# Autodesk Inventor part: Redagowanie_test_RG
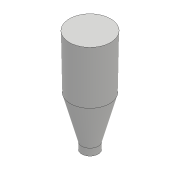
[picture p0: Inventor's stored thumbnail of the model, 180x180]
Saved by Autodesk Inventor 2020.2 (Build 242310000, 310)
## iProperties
Created: 2015-11
Part Number: Redagowanie_test_RG
Material: Ogólne
Document SubType Name: Modeling
Designer: F.Stasiak
Density: 1 g/cm^3
Appearance: Domyślne
Catalog Web Link: www.expertbooks.pl
Manager: www.cadconsulting.pl
Company: Fabian Stasiak CAD Consulting
Author: F.Stasiak
Subject: Zbiór ćwiczeń. Autodesk Inventor 2020. Kurs Professional
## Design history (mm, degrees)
node "Położenie przewężki 1_PZ:1"
node "Element klienta1"
node "Bryła1"
sketch "Szkic1"
  geometry: L1 (-0.6, 0)-(0.6, 0); L2 (-0.6, 0.5)-(-1.432, 3.605); L3 (0.6, 0.5)-(1.432, 3.605); L4 (-0.6, 0)-(-0.6, 0.5); L5 (0.6, 0)-(0.6, 0.5); L6 (-1.5, 7.5)-(1.5, 7.5); L7 (-1.432, 3.605)-(-1.5, 7.5); L8 (1.432, 3.605)-(1.5, 7.5); L9 (0, 7.5)-(0, 0); 3 further points
  constraints: 18 end point, 6 midpoint, 2 horizontal, 2 vertical, 1 coincident, 1 parallel, 1 vertical alignment
  dimensions: "d0" = 1.2 distance of L1.start L1.end; "d1" = 0.5 distance of L1.start L2.start; "d2" = 7.5 distance between parallel lines of L6 L1; "d3" = 7.5 distance from line of L6 point (0, 0); "d4" = 3 distance of L6.start L6.end; "d5" = 89 deg angle of L6 L7; "d6" = 89 deg angle of L6 L8 (= d5); "d7" = 15 deg angle of L2 L9; "d8" = 15 deg angle of L3 L9 (= d7)
revolve "Obrót1" stored, may be unused: angle "d9" = 0 deg
